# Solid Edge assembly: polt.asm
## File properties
Author: Mac
Template: Normal.asm
Last saved by: Mac
Revision: 3
Application: Solid Edge
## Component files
pulk.par
splint.par
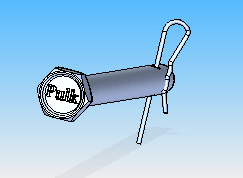
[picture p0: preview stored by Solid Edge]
